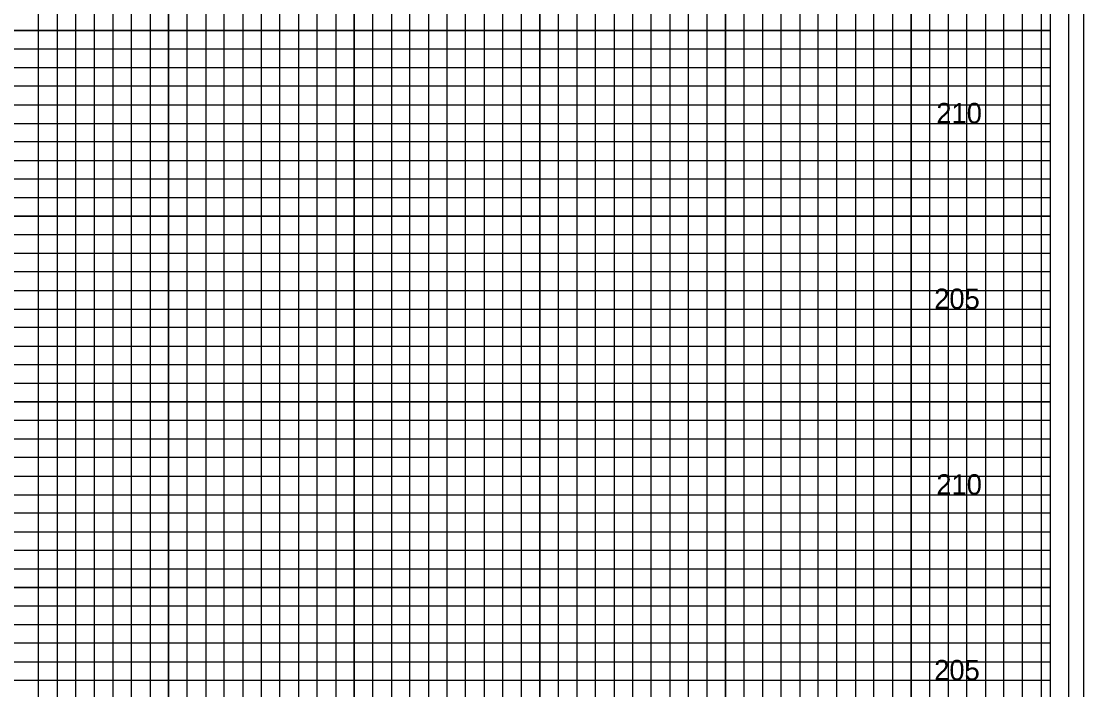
# Model space of a CAD drawing. Extents: x -4 to 103, y -2 to 492.
# Drawn here: x 74.78 to 103.4, y 103.07 to 121.08 of the extents above; entities that cross this region are included whole.
import ezdxf

# ---------------------------------------------------------------- set-up
doc = ezdxf.new("R2010")
doc.units = 0
for name, color, linetype in [('Old_Level_10', 7, 'Continuous'), ('Old_Level_5', 7, 'Continuous'), ('Old_Level_8', 7, 'Continuous'), ('Prop Dimension', 7, 'Continuous'), ('Prop XS Finish Grade Earthwork', 7, 'Continuous'), ('Prop XS SE Text', 7, 'Continuous'), ('Prop XSC Text', 7, 'Continuous')]:
    doc.layers.add(name, color=color, linetype=linetype)

msp = doc.modelspace()

# ---------------------------------------------------------------- linework, layer by layer
at = {"layer": 'Old_Level_10'}
for p, q in [((91.25, 70.825), (91.25, 134.25)), ((93.75, 70.825), (93.75, 134.25)), ((96.25, 70.825), (96.25, 134.25)), ((98.75, 70.825), (98.75, 134.25)), ((101.25, 70.825), (101.25, 134.25)), ((76.25, 70.825), (76.25, 132.825)), ((78.75, 70.825), (78.75, 132.825)), ((81.25, 70.825), (81.25, 132.825)), ((83.75, 70.825), (83.75, 132.825)), ((86.25, 70.825), (86.25, 132.825)), ((88.75, 70.825), (88.75, 132.825)), ((0, 120.825), (102.5, 120.825)), ((0, 118.325), (102.5, 118.325)), ((0, 115.825), (102.5, 115.825)), ((0, 113.325), (102.5, 113.325)), ((0, 110.825), (102.5, 110.825)), ((0, 108.325), (102.5, 108.325)), ((0, 105.825), (102.5, 105.825)), ((0, 103.325), (102.5, 103.325))]:
    msp.add_line(p, q, dxfattribs=at)
at = {"layer": 'Old_Level_5'}
msp.add_lwpolyline([(103.4, 138.225), (-3.5, 138.225), (-3.5, 68.4), (103.4, 68.4)], close=True, dxfattribs=at)
at = {"layer": 'Old_Level_8'}
for points in [[(91.25, 70.825), (91.25, 134.25), (93.75, 134.25), (93.75, 70.825)], [(96.25, 70.825), (96.25, 134.25), (98.75, 134.25), (98.75, 70.825)], [(101.25, 70.825), (101.25, 134.25)], [(76.25, 70.825), (76.25, 132.825), (78.75, 132.825), (78.75, 70.825)], [(81.25, 70.825), (81.25, 132.825), (83.75, 132.825), (83.75, 70.825)], [(86.25, 70.825), (86.25, 132.825), (88.75, 132.825), (88.75, 70.825)], [(0, 118.325), (102.5, 118.325), (102.5, 120.825), (0, 120.825)], [(0, 113.325), (102.5, 113.325), (102.5, 115.825), (0, 115.825)], [(0, 108.325), (102.5, 108.325), (102.5, 110.825), (0, 110.825)], [(0, 103.325), (102.5, 103.325), (102.5, 105.825), (0, 105.825)]]:
    msp.add_lwpolyline(points, dxfattribs=at)
at = {"layer": 'Prop Dimension'}
for points in [[(90.25, 70.825), (90.25, 134.25), (90.75, 134.25), (90.75, 70.825)], [(91.75, 70.825), (91.75, 134.25), (92.25, 134.25), (92.25, 70.825)], [(92.75, 70.825), (92.75, 134.25), (93.25, 134.25), (93.25, 70.825)], [(94.25, 70.825), (94.25, 134.25), (94.75, 134.25), (94.75, 70.825)], [(95.25, 70.825), (95.25, 134.25), (95.75, 134.25), (95.75, 70.825)], [(96.75, 70.825), (96.75, 134.25), (97.25, 134.25), (97.25, 70.825)], [(97.75, 70.825), (97.75, 134.25), (98.25, 134.25), (98.25, 70.825)], [(99.25, 70.825), (99.25, 134.25), (99.75, 134.25), (99.75, 70.825)], [(100.25, 70.825), (100.25, 134.25)], [(100.25, 134.25), (100.75, 134.25), (100.75, 70.825), (101.75, 70.825), (101.75, 134.25), (102.25, 134.25), (102.25, 70.825)], [(75.25, 70.825), (75.25, 132.825), (75.75, 132.825), (75.75, 70.825)], [(76.75, 70.825), (76.75, 132.825), (77.25, 132.825), (77.25, 70.825)], [(77.75, 70.825), (77.75, 132.825), (78.25, 132.825), (78.25, 70.825)], [(79.25, 70.825), (79.25, 132.825), (79.75, 132.825), (79.75, 70.825)], [(80.25, 70.825), (80.25, 132.825), (80.75, 132.825), (80.75, 70.825)], [(81.75, 70.825), (81.75, 132.825), (82.25, 132.825), (82.25, 70.825)], [(82.75, 70.825), (82.75, 132.825), (83.25, 132.825), (83.25, 70.825)], [(84.25, 70.825), (84.25, 132.825), (84.75, 132.825), (84.75, 70.825)], [(85.25, 70.825), (85.25, 132.825), (85.75, 132.825), (85.75, 70.825)], [(86.75, 70.825), (86.75, 132.825), (87.25, 132.825), (87.25, 70.825)], [(87.75, 70.825), (87.75, 132.825), (88.25, 132.825), (88.25, 70.825)], [(89.25, 70.825), (89.25, 132.825), (89.75, 132.825), (89.75, 70.825)], [(0, 119.825), (102.5, 119.825), (102.5, 120.325), (0, 120.325)], [(0, 118.825), (102.5, 118.825), (102.5, 119.325), (0, 119.325)], [(0, 117.325), (102.5, 117.325), (102.5, 117.825), (0, 117.825)], [(0, 116.325), (102.5, 116.325), (102.5, 116.825), (0, 116.825)], [(0, 114.825), (102.5, 114.825), (102.5, 115.325), (0, 115.325)], [(0, 113.825), (102.5, 113.825), (102.5, 114.325), (0, 114.325)], [(0, 112.325), (102.5, 112.325), (102.5, 112.825), (0, 112.825)], [(0, 111.325), (102.5, 111.325), (102.5, 111.825), (0, 111.825)], [(0, 109.825), (102.5, 109.825), (102.5, 110.325), (0, 110.325)], [(0, 108.825), (102.5, 108.825), (102.5, 109.325), (0, 109.325)], [(0, 107.325), (102.5, 107.325), (102.5, 107.825), (0, 107.825)], [(0, 106.325), (102.5, 106.325), (102.5, 106.825), (0, 106.825)], [(0, 104.825), (102.5, 104.825), (102.5, 105.325), (0, 105.325)], [(0, 103.825), (102.5, 103.825), (102.5, 104.325), (0, 104.325)]]:
    msp.add_lwpolyline(points, dxfattribs=at)
at = {"layer": 'Prop XS SE Text'}
msp.add_lwpolyline([(103, 136.825), (-2.8, 136.825), (-2.8, 69.825), (103, 69.825)], close=True, dxfattribs=at)
at = {"layer": 'Prop XSC Text'}
msp.add_lwpolyline([(102.5, 135.825), (0, 135.825), (0, 70.825), (102.5, 70.825)], close=True, dxfattribs=at)

# ---------------------------------------------------------------- texts
at = {"layer": 'Prop XS Finish Grade Earthwork'}
for s, p in [('210', (99.4296, 118.325)), ('205', (99.3724, 113.325)), ('210', (99.4296, 108.325)), ('205', (99.3724, 103.325))]:
    msp.add_text(s, height=0.55, dxfattribs=at).set_placement(p)

doc.saveas('drawing.dxf')
